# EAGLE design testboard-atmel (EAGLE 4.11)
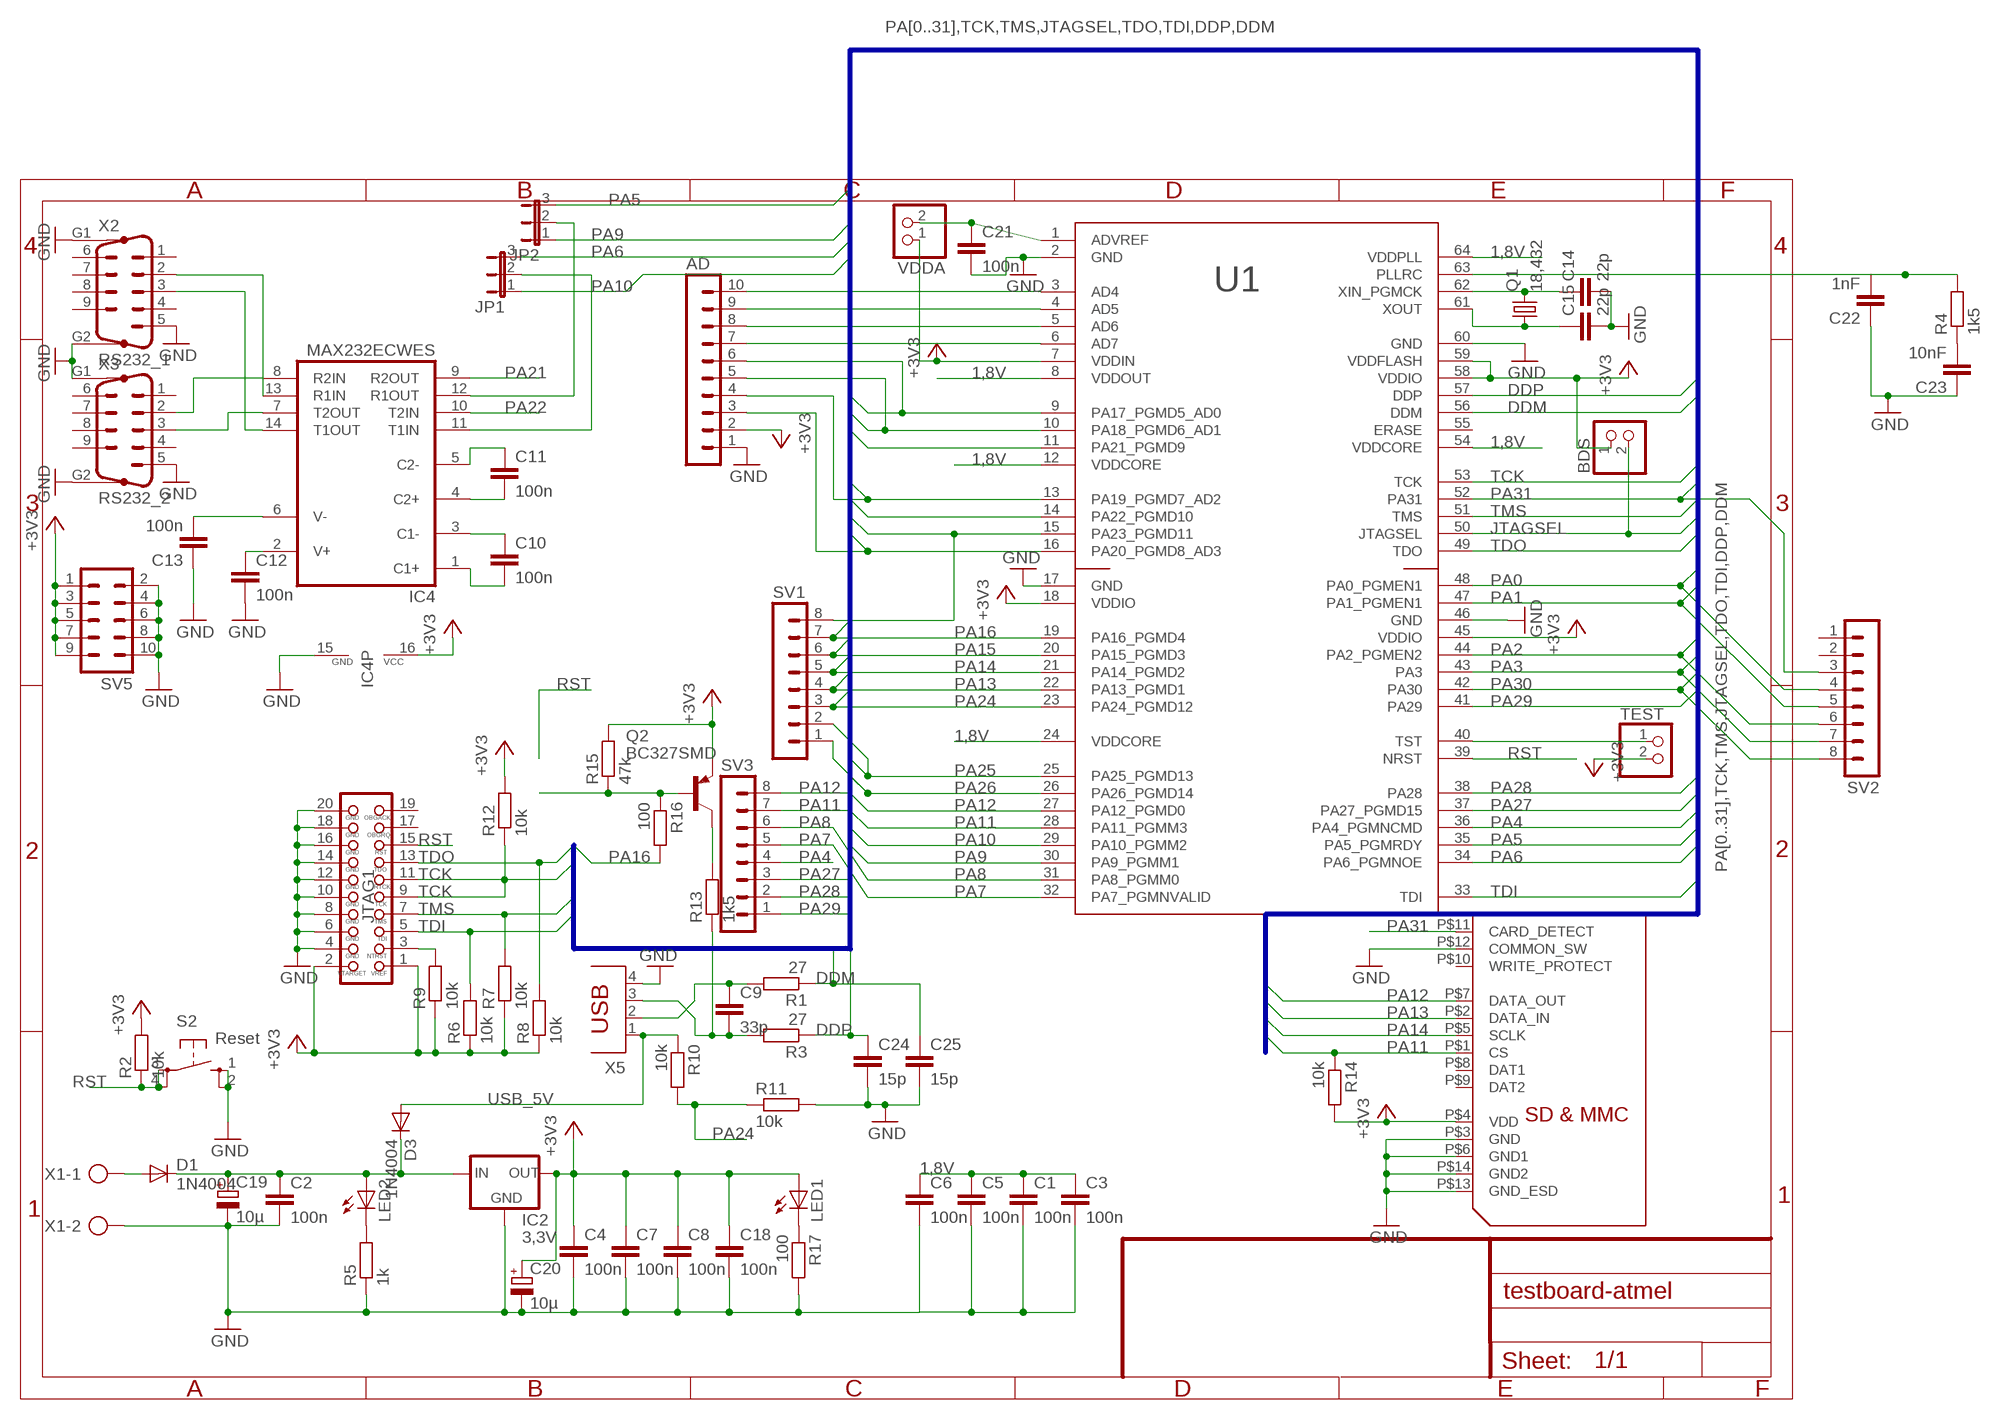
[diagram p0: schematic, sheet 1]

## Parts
AD  MA10-1  [MA10-1]
BDS  PINHD-1X2  [1X02]
C1  100n  C-EUC0805K  [C0805K]
C2  100n  C-EUC0805K  [C0805K]
C3  100n  C-EUC0805K  [C0805K]
C4  100n  C-EUC0805K  [C0805K]
C5  100n  C-EUC0805K  [C0805K]
C6  100n  C-EUC0805K  [C0805K]
C7  100n  C-EUC0805K  [C0805K]
C8  100n  C-EUC0805K  [C0805K]
C9  33p  C-EUC0805K  [C0805K]
C10  100n  C-EUC0805K  [C0805K]
C11  100n  C-EUC0805K  [C0805K]
C12  100n  C-EUC0805K  [C0805K]
C13  100n  C-EUC0805K  [C0805K]
C14  22p  C-EUC0805K  [C0805K]
C15  22p  C-EUC0805K  [C0805K]
C18  100n  C-EUC0805K  [C0805K]
C19  10µ  CPOL-EUE/7260-38W  [E/7260-38W]
C20  10µ  CPOL-EUE/7260-38W  [E/7260-38W]
C21  100n  C-EUC0805K  [C0805K]
C22  1nF  C-EUC0805K  [C0805K]
C23  10nF  C-EUC0805K  [C0805K]
C24  15p  C-EUC0805K  [C0805K]
C25  15p  C-EUC0805K  [C0805K]
D1  1N4004  [DO41-10]
D3  1N4004  [DO41-10]
IC2  3,3V  78XXS  [78XXS]
IC4  MAX232ECWES  [SO16]
JP1  JP2E  [JP2]
JP2  JP2E  [JP2]
JTAG1  JTAG-ARM  [JTAG-ARM]
LED1  LED3MM  [LED3MM]
LED2  LED3MM  [LED3MM]
Q1  18,432  CRYTALHC49U-V  [HC49U-V]
Q2  BC327SMD  [SOT23-BEC]
R1  27  R-EU_M0805  [M0805]
R2  10k  R-EU_M0805  [M0805]
R3  27  R-EU_M0805  [M0805]
R4  1k5  R-EU_M0805  [M0805]
R5  1k  R-EU_M0805  [M0805]
R6  10k  R-EU_M0805  [M0805]
R7  10k  R-EU_M0805  [M0805]
R8  10k  R-EU_M0805  [M0805]
R9  10k  R-EU_M0805  [M0805]
R10  10k  R-EU_M0805  [M0805]
R11  10k  R-EU_M0805  [M0805]
R12  10k  R-EU_M0805  [M0805]
R13  1k5  R-EU_M0805  [M0805]
R14  10k  R-EU_M0805  [M0805]
R15  47k  R-EU_M0805  [M0805]
R16  100  R-EU_M0805  [M0805]
R17  100  R-EU_M0805  [M0805]
S2  Reset  10XX  [B3F-10XX]
SD1  FPS009-2405-0  [FPS009-2405]
SV1  MA08-1  [MA08-1]
SV2  MA08-1  [MA08-1]
SV3  MA08-1  [MA08-1]
SV5  MA05-2  [MA05-2]
TEST  PINHD-1X2  [1X02]
U1  AT91SAM7S64_LQFP64  [LQFP64]
VDDA  PINHD-1X2  [1X02]
X1  AK500/2  [AK500/2]
X2  RS232_1  M09HP  [M09HP]
X3  RS232_2  M09HP  [M09HP]
X5  PN61729  [PN61729]

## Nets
1,8V: C1.1 C3.1 C5.1 C6.1 U1.8(VDDOUT) U1.12(VDDCORE) U1.24(VDDCORE) U1.54(VDDCORE) U1.64(VDDPLL)
+3V3: AD.2 BDS.1 C4.1 C7.1 C8.1 C18.1 C20.+ IC2.OUT IC4.16(VCC) JTAG1.1 JTAG1.2 LED1.A Q2.E R2.2 R6.1 R7.1 R8.1 R9.1 R12.2 R14.2 R15.2 SD1.P$4(VDD) SV5.1 SV5.3 SV5.5 SV5.7 SV5.9 TEST.2 U1.7(VDDIN) U1.18(VDDIO) U1.45(VDDIO) U1.58(VDDIO) U1.59(VDDFLASH) VDDA.1
AD4: AD.10 U1.3(AD4)
AD5: AD.9 U1.4(AD5)
AD6: AD.8 U1.5(AD6)
AD7: AD.7 U1.6(AD7)
DDM: C25.1 R1.1 U1.56(DDM)
DDP: C24.1 R3.1 U1.57(DDP)
JTAGSEL: BDS.2 U1.50(JTAGSEL)
N$1: D1.A X1.1
N$2: C2.1 C19.+ D1.C D3.C IC2.IN LED2.A
N$3: C11.1 IC4.5(C2-)
N$4: C9.2 R3.2 R13.1 X5.3
N$5: TEST.1 U1.40(TST)
N$6: C11.2 IC4.4(C2+)
N$7: C10.1 IC4.3(C1-)
N$8: C10.2 IC4.1(C1+)
N$9: C12.1 IC4.2(V+)
N$10: C13.2 IC4.6(V-)
N$11: C15.1 Q1.1 U1.61(XOUT)
N$12: C14.1 Q1.2 U1.62(XIN_PGMCK)
N$13: LED2.K(C) R5.2
N$14: LED1.K(C) R17.1
N$15: AD.1 C1.2 C2.2 C3.2 C4.2 C5.2 C6.2 C7.2 C8.2 C12.2 C13.1 C14.2 C15.2 C18.2 C19.- C20.- C21.2 C22.1 C23.1 C24.2 C25.2 IC2.GND IC4.15(GND) JTAG1.4 JTAG1.6 JTAG1.8 JTAG1.10 JTAG1.12 JTAG1.14 JTAG1.16 JTAG1.18 JTAG1.20 R5.1 R11.2 R17.2 S2.1 S2.2 SD1.P$3(GND) SD1.P$6(GND1) SD1.P$12(COMMON_SW) SD1.P$13(GND_ESD) SD1.P$14(GND2) SV5.2 SV5.4 SV5.6 SV5.8 SV5.10 U1.2(GND) U1.17(GND) U1.46(GND) U1.60(GND) X1.2 X2.5 X2.G1 X2.G2 X3.5 X3.G1 X3.G2 X5.4 ; supply symbol labelled GND
N$16: IC4.13(R1IN) X2.2
N$17: JTAG1.3 R9.2
N$18: C21.1 U1.1(ADVREF) VDDA.2
N$20: Q2.C R13.2
N$23: Q2.B R15.1 R16.1
N$24: C9.1 R1.2 X5.2
N$26: IC4.14(T1OUT) X2.3
N$27: IC4.8(R2IN) X3.2
N$28: IC4.7(T2OUT) X3.3
N$33: C23.2 R4.1
N$35: C22.2 R4.2 U1.63(PLLRC)
PA0: SV2.4 U1.48(PA0_PGMEN1)
PA1: SV2.5 U1.47(PA1_PGMEN1)
PA2: SV2.6 U1.44(PA2_PGMEN2)
PA3: SV2.7 U1.43(PA3)
PA4: SV3.4 U1.36(PA4_PGMNCMD)
PA5: JP2.3 U1.35(PA5_PGMRDY)
PA6: JP1.3 U1.34(PA6_PGMNOE)
PA7: SV3.5 U1.32(PA7_PGMNVALID)
PA8: SV3.6 U1.31(PA8_PGMM0)
PA9: JP2.1 U1.30(PA9_PGMM1)
PA10: JP1.1 U1.29(PA10_PGMM2)
PA11: R14.1 SD1.P$1(CS) SV3.7 U1.28(PA11_PGMM3)
PA12: SD1.P$7(DATA_OUT) SV3.8 U1.27(PA12_PGMD0)
PA13: SD1.P$2(DATA_IN) SV1.4 U1.22(PA13_PGMD1)
PA14: SD1.P$5(SCLK) SV1.5 U1.21(PA14_PGMD2)
PA15: SV1.6 U1.20(PA15_PGMD3)
PA16: R16.2 SV1.7 U1.19(PA16_PGMD4)
PA17: AD.6 U1.9(PA17_PGMD5_AD0)
PA18: AD.5 U1.10(PA18_PGMD6_AD1)
PA19: AD.4 U1.13(PA19_PGMD7_AD2)
PA20: AD.3 U1.16(PA20_PGMD8_AD3)
PA21: IC4.9(R2OUT) U1.11(PA21_PGMD9)
PA22: IC4.10(T2IN) U1.14(PA22_PGMD10)
PA23: SV1.8 U1.15(PA23_PGMD11)
PA24: R10.2 R11.1 SV1.3 U1.23(PA24_PGMD12)
PA25: SV1.2 U1.25(PA25_PGMD13)
PA26: SV1.1 U1.26(PA26_PGMD14)
PA27: SV3.3 U1.37(PA27_PGMD15)
PA28: SV3.2 U1.38(PA28)
PA29: SV3.1 U1.41(PA29)
PA30: SV2.8 U1.42(PA30)
PA31: SD1.P$11(CARD_DETECT) SV2.3 U1.52(PA31)
R1OUT: IC4.12(R1OUT) JP2.2
RST: JTAG1.15 R2.1 S2.3 S2.4 U1.39(NRST)
T1IN: IC4.11(T1IN) JP1.2
TCK: JTAG1.9 JTAG1.11 R12.1 U1.53(TCK)
TDI: JTAG1.5 R6.2 U1.33(TDI)
TDO: JTAG1.13 R8.2 U1.49(TDO)
TMS: JTAG1.7 R7.2 U1.51(TMS)
USB_5V: D3.A R10.1 X5.1
Unconnected: JTAG1.17 JTAG1.19 SD1.P$8(DAT1) SD1.P$9(DAT2) SD1.P$10(WRITE_PROTECT) SV2.1 SV2.2 U1.55(ERASE) X2.1 X2.4 X2.6 X2.7 X2.8 X2.9 X3.1 X3.4 X3.6 X3.7 X3.8 X3.9

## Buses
PA[0..31],TCK,TMS,JTAGSEL,TDO,TDI,DDP,DDM

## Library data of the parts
AD = con-lstb:MA10-1: PIN HEADER
BDS TEST VDDA = pinhead:PINHD-1X2: PIN HEADER
C1-C15 C18 C21-C25 = rcl:C-EU: CAPACITOR, European symbol
C19 C20 = rcl:CPOL-EU: POLARIZED CAPACITOR, European symbol
D1 D3 = diode:1N4004: DIODE
IC2 = v-reg:78XXS: VOLTAGE REGULATOR
IC4 = maxim-6b:MAX232ECWE: RS232 TRANSEIVER
JP1 JP2 = jumper:JP2E: JUMPER
JTAG1 = philips-6:JTAG-ARM
LED1 LED2 = led:LED: LED
Q1 = crystal:CRYTAL: CRYSTAL
Q2 = transistor-pnp:BC327*: PNP Transistror
R1-R17 = rcl:R-EU_: RESISTOR, European symbol
S2 = KEY_B:10XX
SD1 = con-yamaichi:FPS009-2405-0
SV1-SV3 = con-lstb:MA08-1: PIN HEADER
SV5 = con-lstb:MA05-2: PIN HEADER
U1 = atmel_prototype_header:AT91SAM7S64: Atmel AT91 ARM Thumb-based Microcontroller. LQFP64 package.
X1 = con-ptr500:AK500/2: CONNECTOR
X2 X3 = con-subd:M09HP: SUB-D
X5 = con-berg:PN61729: BERG

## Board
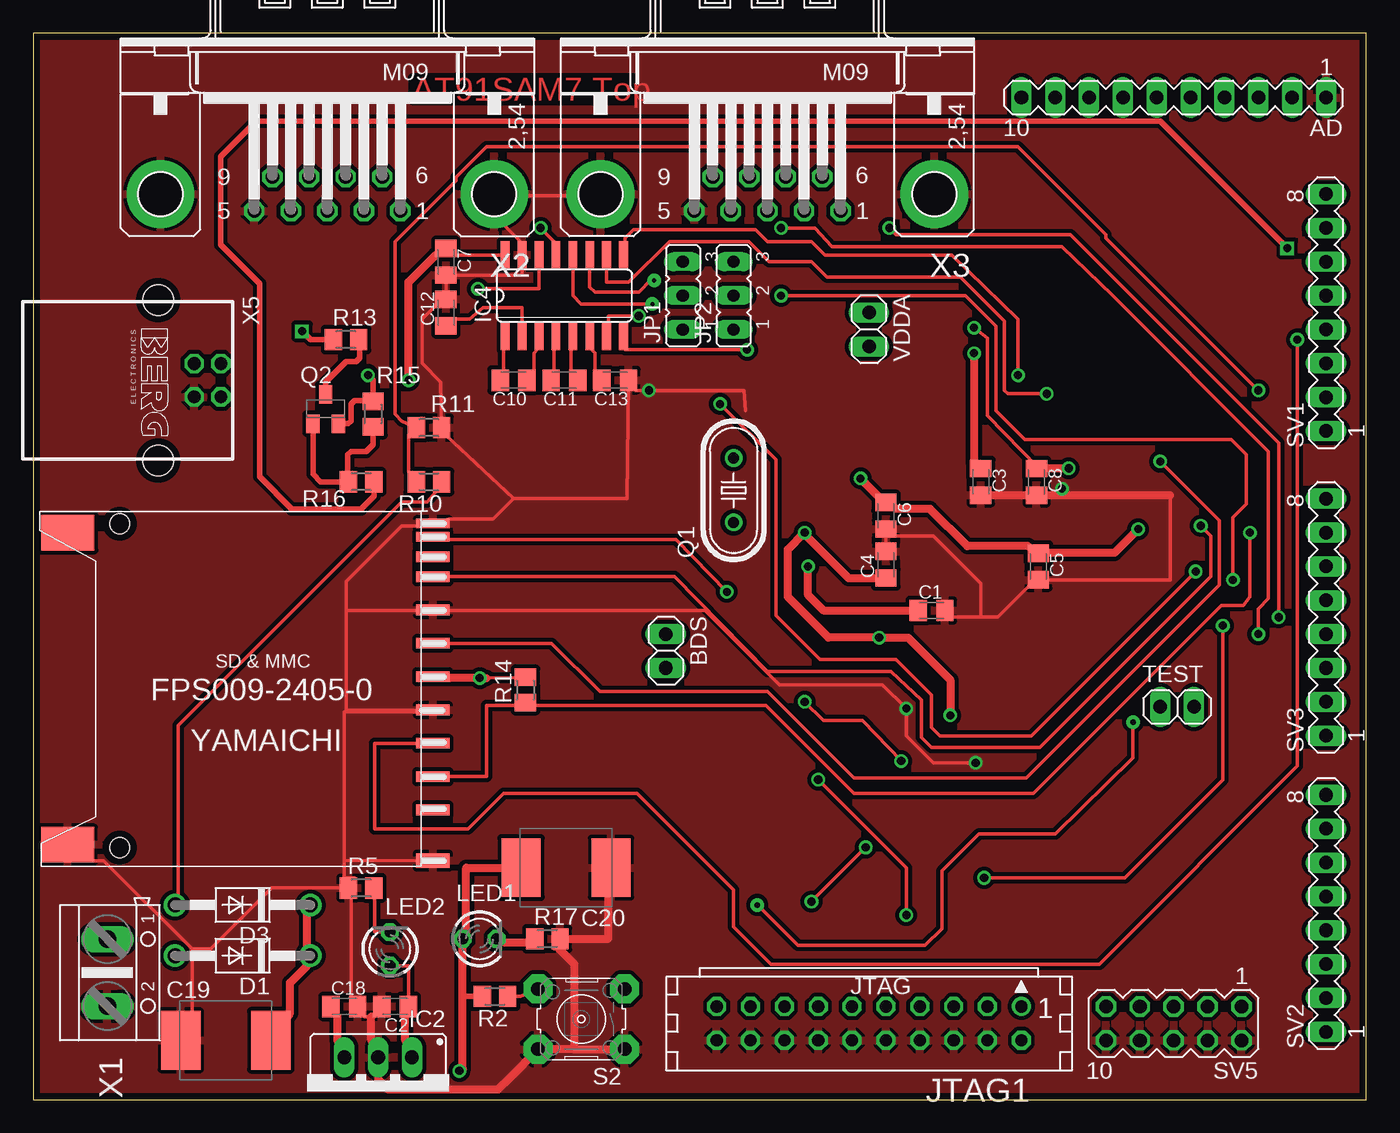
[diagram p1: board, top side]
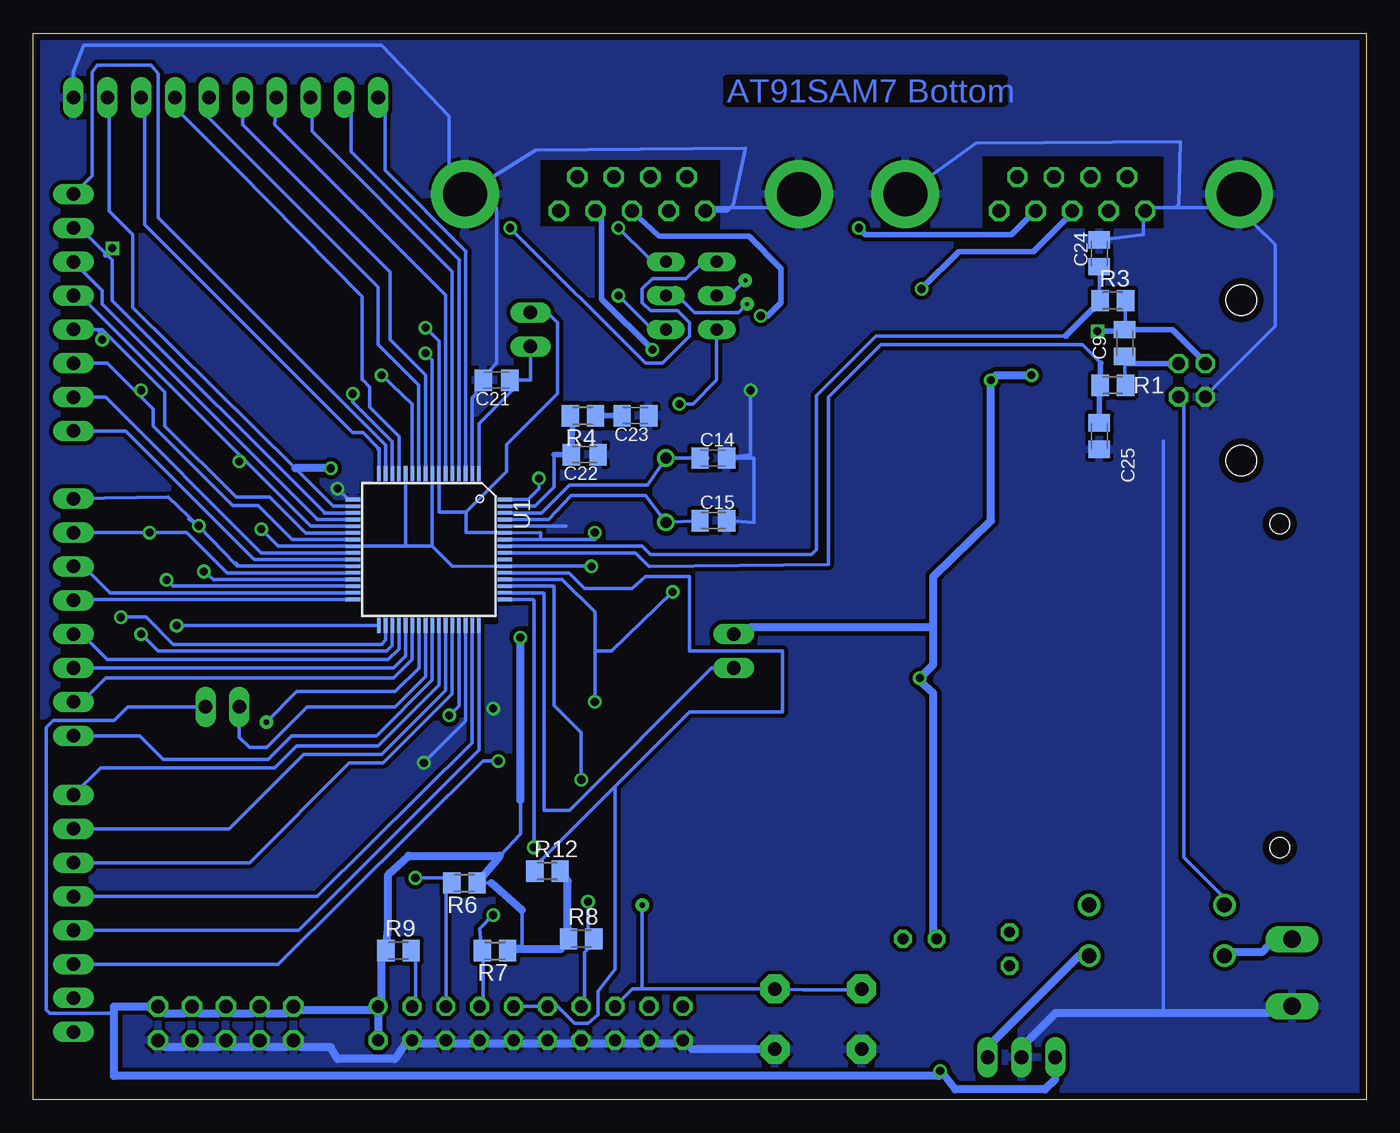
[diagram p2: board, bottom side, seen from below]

Size 100 x 80 mm. Coordinates in mm from the lower left corner, seen from the top.
Outline: 0,0 100,0 100,80 0,80 0,0
Copper layers (1*16): Top 0.035mm / dielectric 1.5mm / Bottom 0.035mm
Design rules "default": minimum track width 8mil, minimum drill 24mil, track to track 12mil, track to pad 12mil, pad to pad 8mil, via to via 12mil, smd to smd 8mil, copper to edge 20mil, drill to drill 8mil, minimum pad ring 10mil, minimum via ring 8mil, stop-mask expansion 4mil, vias tented up to drill 0mil, thermal gap 10mil
bRestrict: area 65.1,36.1 to 75.5,46.4; area 15.2,65.4 to 28.8,70.7; area 48.5,65.5 to 61.9,70.5; area 65.1,35.7 to 75.5,46
vRestrict: area 34.8,57.8 to 44.9,62.9; area 13.2,1.9 to 15.7,7; area 37.3,15.9 to 39.8,20.9

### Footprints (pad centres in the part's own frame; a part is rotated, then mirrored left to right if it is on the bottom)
MA10-1 = drill 1.016 long: 1 -11.43,0; 2 -8.89,0; 3 -6.35,0; 4 -3.81,0; 5 -1.27,0; 6 1.27,0; 7 3.81,0; 8 6.35,0; 9 8.89,0; 10 11.43,0
1X02 = drill 1.016 long: 1 -1.27,0; 2 1.27,0
C0805K = smd 1.3 x 1.6: 1 -1,0; 2 1,0
E/7260-38W = smd 2.95 x 4.4: + 3.375,0; - -3.375,0
DO41-10 = drill 1.118 round: A 5.08,0; C -5.08,0
78XXS = drill 1.016 long: GND 0,-2.54; IN -2.54,-2.54; OUT 2.54,-2.54
SO16 = smd 0.66 x 2.032: 1 -4.445,-3.073; 2 -3.175,-3.073; 3 -1.905,-3.073; 4 -0.635,-3.073; 5 0.635,-3.073; 6 1.905,-3.073; 7 3.175,-3.073; 8 4.445,-3.073; 9 4.445,3.073; 10 3.175,3.073; 11 1.905,3.073; 12 0.635,3.073; 13 -0.635,3.073; 14 -1.905,3.073; 15 -3.175,3.073; 16 -4.445,3.073
JP2 = drill 0.914 long: 1 -2.54,0; 2 0,0; 3 2.54,0
JTAG-ARM = drill 0.914 round: 1 -11.43,-1.27 | drill 0.914 octagon: 2 -11.43,1.27; 3 -8.89,-1.27; 4 -8.89,1.27; 5 -6.35,-1.27; 6 -6.35,1.27; 7 -3.81,-1.27; 8 -3.81,1.27; 9 -1.27,-1.27; 10 -1.27,1.27; 11 1.27,-1.27; 12 1.27,1.27; 13 3.81,-1.27; 14 3.81,1.27; 15 6.35,-1.27; 16 6.35,1.27; 17 8.89,-1.27; 18 8.89,1.27; 19 11.43,-1.27; 20 11.43,1.27
LED3MM = drill 0.813 octagon: A -1.27,0; K 1.27,0
HC49U-V = drill 0.813 round: 1 -2.413,0; 2 2.413,0
SOT23-BEC = smd 1 x 1.4: B -0.95,-1.1; C 0,1.1; E 0.95,-1.1
M0805 = smd 1.3 x 1.6: 1 -0.95,0; 2 0.95,0
B3F-10XX = drill 1.016 pad 2.159 octagon: 1 -3.379,2.312; 2 3.123,2.312; 3 -3.379,-2.209; 4 3.123,-2.209
FPS009-2405 = smd 2.5 x 0.8: P$1 -13,6.88; P$2 -13,4.38; P$3 -13,1.88; P$4 -13,-0.62; P$5 -13,-3.12; P$6 -13,-5.62; P$7 -13,-8.12; P$8 -13,-9.62; P$9 -13,9.38 | smd 4 x 2.65: P$10 14.4,-11.42; P$14 14.4,11.98 | smd 2.5 x 0.7: P$11 -13,-11.12; P$12 -13,-12.12 | smd 2.5 x 1.1: P$13 -13,13.18 | hole 1.5: 10.5,12.2; 10.5,-12.1
MA08-1 = drill 1.016 long: 1 -8.89,0; 2 -6.35,0; 3 -3.81,0; 4 -1.27,0; 5 1.27,0; 6 3.81,0; 7 6.35,0; 8 8.89,0
MA05-2 = drill 1.016 octagon: 1 -5.08,-1.27; 2 -5.08,1.27; 3 -2.54,-1.27; 4 -2.54,1.27; 5 0,-1.27; 6 0,1.27; 7 2.54,-1.27; 8 2.54,1.27; 9 5.08,-1.27; 10 5.08,1.27
LQFP64 = smd 1.1 x 0.285: 1 -5.7,3.75; 2 -5.7,3.25; 3 -5.7,2.75; 4 -5.7,2.25; 5 -5.7,1.75; 6 -5.7,1.25; 7 -5.7,0.75; 8 -5.7,0.25; 9 -5.7,-0.25; 10 -5.7,-0.75; 11 -5.7,-1.25; 12 -5.7,-1.75; 13 -5.7,-2.25; 14 -5.7,-2.75; 15 -5.7,-3.25; 16 -5.7,-3.75; 33 5.7,-3.75; 34 5.7,-3.25; 35 5.7,-2.75; 36 5.7,-2.25; 37 5.7,-1.75; 38 5.7,-1.25; 39 5.7,-0.75; 40 5.7,-0.25; 41 5.7,0.25; 42 5.7,0.75; 43 5.7,1.25; 44 5.7,1.75; 45 5.7,2.25; 46 5.7,2.75; 47 5.7,3.25; 48 5.7,3.75 | smd 0.285 x 1.1: 17 -3.75,-5.7; 18 -3.25,-5.7; 19 -2.75,-5.7; 20 -2.25,-5.7; 21 -1.75,-5.7; 22 -1.25,-5.7; 23 -0.75,-5.7; 24 -0.25,-5.7; 25 0.25,-5.7; 26 0.75,-5.7; 27 1.25,-5.7; 28 1.75,-5.7; 29 2.25,-5.7; 30 2.75,-5.7; 31 3.25,-5.7; 32 3.75,-5.7; 49 3.75,5.7; 50 3.25,5.7; 51 2.75,5.7; 52 2.25,5.7; 53 1.75,5.7; 54 1.25,5.7; 55 0.75,5.7; 56 0.25,5.7; 57 -0.25,5.7; 58 -0.75,5.7; 59 -1.25,5.7; 60 -1.75,5.7; 61 -2.25,5.7; 62 -2.75,5.7; 63 -3.25,5.7; 64 -3.75,5.7
AK500/2 = drill 1.321 long: 1 -2.515,0; 2 2.515,0
M09HP = drill 1.016 octagon: 1 -5.486,1.27; 2 -2.743,1.27; 3 0,1.27; 4 2.743,1.27; 5 5.486,1.27; 6 -4.115,-1.27; 7 -1.372,-1.27; 8 1.372,-1.27; 9 4.115,-1.27 | drill 3.302 pad 5.08 round: G1 -12.522,0; G2 12.522,0
PN61729 = drill 0.95 octagon: 1 1.25,4.71; 2 -1.25,4.71; 3 -1.25,2.71; 4 1.25,2.71 | hole 2.3: -6.02,0; 6.02,0

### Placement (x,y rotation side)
AD  85.56,75.18 180 top
BDS  47.46,33.65 270 top
C1  67.4,36.7 0 top
C2  27.14,6.98 180 top
C3  71.08,46.35 270 top
C4  63.97,40.13 90 top
C5  75.4,40 270 top
C6  63.97,43.81 270 top
C7  30.95,62.86 270 top
C8  75.27,46.35 270 top
C9  18.12,56.76 90 bottom
C10  36.03,53.97 180 top
C11  39.84,53.97 180 top
C12  30.95,59.05 90 top
C13  43.65,53.97 180 top
C14  48.98,48.13 0 bottom
C15  48.98,43.43 0 bottom
C18  23.33,6.98 0 top
C19  14.44,4.44 0 top
C20  39.97,17.39 180 top
C21  65.24,53.97 180 bottom
C22  58.64,48.38 180 bottom
C23  54.83,51.3 180 bottom
C24  20.03,63.5 90 bottom
C25  20.03,49.78 270 bottom
D1  15.71,10.79 180 top
D3  15.71,14.6 180 top
IC2  25.87,0.63 180 top
IC4  39.84,60.32 0 top
JP1  48.73,60.32 90 top
JP2  52.54,60.32 90 top
JTAG1  62.7,5.71 180 top
LED1  33.49,12.06 0 top
LED2  26.76,11.3 90 top
Q1  52.54,45.72 90 top
Q2  21.93,51.81 0 top
R1  19.01,53.59 0 bottom
R2  34.63,7.74 180 top
R3  19.01,59.94 0 bottom
R4  58.76,51.3 180 bottom
R5  24.6,15.87 0 top
R6  67.65,16.25 180 bottom
R7  65.37,11.17 180 bottom
R8  58.89,12.06 0 bottom
R9  72.61,11.17 0 bottom
R10  29.68,46.35 180 top
R11  29.68,50.41 0 top
R12  61.43,17.14 0 bottom
R13  23.46,57.02 0 top
R14  36.92,30.73 90 top
R15  25.49,51.43 90 top
R16  24.6,46.35 0 top
R17  38.57,12.06 0 top
S2  40.98,6.09 180 top
SD1  16.98,31.11 180 top
SV1  96.99,59.05 90 top
SV2  96.99,13.97 90 top
SV3  96.99,36.19 90 top
SV5  85.56,5.71 180 top
TEST  85.81,29.46 0 top
U1  70.32,41.27 270 bottom
VDDA  62.7,57.78 270 top
X1  5.55,9.52 270 top
X2  22.06,67.94 180 top
X3  55.08,67.94 180 top
X5  9.36,53.97 270 top

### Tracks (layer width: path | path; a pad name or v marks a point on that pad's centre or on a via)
1,8V  (via drill 0.61)
  Top 0.254: 74.64,41.52 C5.1 75.4,41.02 | 64.73,44.32 C6.1 63.86,44.81 | C3.1 71.08,47.37 70.57,47.75
  Top 0.61: 74.64,41.52 70.07,41.52 67.27,44.32 64.73,44.32 | 63.86,44.81 v62.06,46.6 | v70.57,56 70.57,47.75 | v58.13,40 58.13,37.84 59.27,36.7 C1.1 | v82.89,42.79 81.11,41.02 75.4,41.02
  Bottom 0.254: 70.07,41.52 68.54,40 U1.54 57.89,40.02 v58.13,40 | 70.07,41.52 70.07,46.6 U1.8 70.07,47.37 70.07,55.49 v70.57,56 | 70.07,41.52 72.1,41.52 | 72.1,41.52 75.65,41.52 U1.24 76.03,41.52 81.62,41.52 v82.89,42.79 | U1.12 72.07,41.55 72.1,41.52 | U1.64 62.89,45.02 62.06,45.84 v62.06,46.6
+3V3  (via drill 0.61)
  Top 0.254: 22.82,6.22 C18.1 | LED1.A 32.47,12.57 | 34,31.62 R14.2 | 31.2,31.62 SD1.P$4 | IC4.16 35.27,63.37 31.71,63.37 C7.1 30.19,63.37 | C8.1 75.27,47.37 75.4,47.37 71.59,51.3 71.59,57.15 v70.57,57.91 | v57.87,42.54 57.87,42.41
  Top 0.406: Q2.E 23.63,50.71 23.84,50.92 23.84,52.19 24.09,52.45 25.36,52.45 25.43,52.38 R15.2 25.49,53.97 v25.11,54.35 | v31.97,2.15 32.22,2.41 32.22,2.28 | 32.22,7.74 R2.2
  Top 0.61: 22.82,6.22 22.82,4.44 IC2.OUT | 32.22,2.28 32.22,7.74 LED1.A | 32.47,12.57 32.47,17.39 C20.+ | 31.2,31.62 v33.49,31.62 34,31.62 | 30.19,63.37 28.16,61.34 v28.16,53.97 | 75.4,47.37 v77.69,47.37 | C4.1 61.16,39.13 57.87,42.41 | v68.8,28.82 68.8,31.49 65.62,34.67 v63.46,34.67 59.65,34.67 56.6,37.71 56.6,41.27 v57.87,42.54
  Bottom 0.254: 23.33,1.52 IC2.OUT | 46.19,35.43 BDS.1 | VDDA.1 61.43,59.05 60.67,58.29 60.67,52.95 64.48,49.14 64.48,47.11 67.53,44.06 | AD.2 94.32,75.31 94.32,66.67 92.55,64.89 92.55,59.43 80.35,47.37 77.51,44.52 U1.18 | 73.88,11.3 R9.1 | 73.88,7.49 JTAG1.1 74.64,6.73 | 80.99,6.47 SV5.9 79.97,6.73 | SV5.7 82.51,6.47 | 87.59,6.47 SV5.3 88.61,6.47 | 86.07,6.47 SV5.5 | 90.13,6.47 SV5.1 90.64,7.11 90.77,7.11 90.77,6.98 | 60.41,11.3 R8.1 59.91,12.82 | 63.72,11.3 R7.1 | 61.94,42.03 61.94,42.54 U1.59 64.99,42.54 67.53,42.54 67.53,44.06 | v57.87,42.54 57.87,42.03 61.94,42.03 | 61.94,42.03 U1.58 | 63.34,14.22 63.34,11.3 | R6.1 65.62,16.25 | 32.22,2.41 v31.97,2.15 31.84,2.03 32.09,1.77 | U1.45 68.07,29.55 v68.8,28.82 | 67.53,44.06 69.56,44.06 69.56,46.6 U1.7 69.57,56.9 v70.57,57.91 | v28.16,53.97 27.77,54.35 | 63.46,22.47 63.46,19.93 64.99,18.28 | TEST.2 92.93,29.46 93.94,28.44 98.51,28.44 99.02,27.93 99.02,6.73 98.77,6.47 93.94,6.47
  Bottom 0.61: 23.33,1.52 24.09,0.76 30.82,0.76 31.84,2.03 | 32.47,35.43 46.19,35.43 | v28.16,53.97 28.16,43.43 32.47,39.24 32.47,35.43 | 32.47,35.43 32.47,32.63 v33.49,31.62 33.49,31.36 32.47,30.47 32.47,12.57 LED1.A | 73.88,7.49 73.88,11.3 | 82.51,6.47 80.99,6.47 | SV5.5 85.05,6.47 83.53,6.47 SV5.7 | 87.59,6.47 86.07,6.47 | 90.13,6.47 88.61,6.47 | 79.97,6.73 74.64,6.73 | 63.34,11.3 63.72,11.3 | 63.34,11.3 60.41,11.3 | 59.91,12.82 59.91,16.38 R12.2 | 63.46,22.47 v63.46,34.67 | R6.1 64.99,18.28 71.84,18.28 73.37,16.89 73.37,12.82 R9.1 | 65.62,16.25 63.34,14.22 | 63.34,11.3 R7.1 | v77.69,47.37 80.35,47.37 | 27.77,54.35 v25.11,54.35 | JTAG1.1 JTAG1.2 | 32.09,1.77 93.94,1.77 93.94,6.47 93.94,6.98 90.77,6.98
AD4
  Bottom 0.254: AD.10 73.62,75.56 73.62,69.72 67.53,63.62 67.57,63.58 U1.3
AD5
  Bottom 0.254: 68.07,63.02 68.03,62.99 | AD.9 76.16,75.56 76.16,71.11 68.16,63.11 68.07,63.02 | U1.4 68.07,63.02
AD6
  Bottom 0.254: AD.8 79.08,75.31 79.08,72.64 68.57,62.13 U1.5
AD7
  Bottom 0.254: 81.62,75.43 AD.7 81.88,73.15 69.07,60.34 U1.6
DDM
  Bottom 0.254: U1.56 64.22,41.02 54.83,41.02 53.81,40 40.35,40.13 40.35,52.7 36.41,56.64 21.3,56.64 19.9,55.24
  Bottom 0.406: C25.1 20.03,53.59 R1.1 19.96,55.18 19.9,55.24
DDP
  Bottom 0.254: 22.5,57.27 36.79,57.27 41.24,52.83 41.24,41.27 41.62,40.89 53.68,40.89 54.32,41.52 64.22,41.52 U1.57 | C24.1 20.03,59.81 R3.1 | 19.9,59.81 19.77,59.81
  Bottom 0.406: R3.1 19.9,59.81 20.41,59.3 20.54,59.3 22.57,57.27 22.5,57.27
JTAGSEL
  Bottom 0.254: BDS.2 49.11,32.38 59.78,21.71 61.68,21.71 61.68,37.97 61.74,38.02 U1.50
N$1
  Bottom 0.61: D1.A 9.87,11.04 7.84,11.04 7.33,11.55 X1.1
N$2
  Top 0.254: 27.9,6.22 C2.1 28.16,7.74 28.16,10.03 LED2.A | IC2.IN 27.9,4.44
  Top 0.61: 27.9,4.44 27.9,6.22 | D3.C 20.54,13.84 20.54,11.55 D1.C 20.54,10.03 19.27,8.76 19.27,6.47 C19.+
  Bottom 0.254: D1.C 21.55,10.79
  Bottom 0.61: 21.55,10.79 27.9,4.44 IC2.IN
N$3
  Top 0.254: C11.1 40.35,54.73 40.35,56.26 IC4.5
N$4  (via drill 0.61)
  Top 0.406: R13.1 20.79,57.02 v20.15,57.65
  Bottom 0.254: C9.2 18.12,57.65 18.12,57.4 18.06,57.4 R3.2
  Bottom 0.406: X5.3 12.05,55.22 12.03,55.24 14.55,57.76 C9.2 | 18.12,57.65 v20.15,57.65
N$5
  Bottom 0.254: U1.40 70.57,35.17 70.57,31.74 72.86,29.46 79.46,29.46 82.51,26.41 83.78,26.41 84.54,27.17 TEST.1
N$6
  Top 0.254: C11.2 39.08,54.73 39.08,56.26 IC4.4
N$7
  Top 0.254: C10.1 37.55,54.73 37.55,56 37.81,56.26 IC4.3
N$8
  Top 0.254: C10.2 35.27,54.73 35.27,56.26 IC4.1
N$9
  Top 0.254: C12.1 31.71,58.54 32.73,58.54 33.74,59.43 36.66,59.43 IC4.2
N$10
  Top 0.254: C13.2 42.13,54.73 42.13,56 41.87,56.26 IC4.6
N$11
  Bottom 0.254: C15.1 Q1.1 54.06,45.33 59.65,45.33 61.34,43.52 U1.61
N$12
  Bottom 0.254: 49.37,48.13 C14.1 Q1.2 53.94,46.1 59.78,46.1 61.85,44.02 U1.62
N$13
  Top 0.254: R5.2 25.62,15.11 25.62,12.57 LED2.K
N$14
  Top 0.254: 37.05,11.81 R17.1
  Top 0.61: 37.05,11.81 35.27,11.81 LED1.K
N$15  (via drill 0.61, 0.61 pad 1.02)
  Top 0.254: X3.G2 40.22,67.81 37.17,67.81 X2.G1 35.27,65.65 36.54,64.38 IC4.15 36.66,61.84 31.71,61.84 C7.2 C12.2 30.19,59.56 29.17,58.54 29.17,55.24 30.57,53.84 R11.2 30.31,50.41 36.03,45.08 | 43.14,15.11 42.76,16.76 C20.- | R17.2 39.08,11.3 39.46,11.3 | 11.9,11.3 5.3,17.9 4.53,17.9 SD1.P$14 | 11.9,11.3 11.9,6.47 C19.- | C2.2 25.62,6.22 25.36,6.22 24.85,6.22 C18.2 23.84,7.74 23.84,15.11 R5.1 | 23.33,17.9 23.33,16.63 24.09,16.63 R5.1 | 23.33,17.9 SD1.P$13 | 25.36,4.44 IC2.GND 25.87,1.52 | 11.9,11.3 13.3,11.3 17.87,15.87 R5.1 | 71.08,36.19 72.35,36.19 74.64,38.48 C5.2 75.4,38.98 85.31,38.98 85.31,45.33 | 71.08,36.19 69.05,36.19 68.54,36.7 C1.2 | 53.43,51.68 53.3,53.21 v46.19,53.21 45.17,53.21 C13.1 44.54,45.08 36.03,45.08 | 71.08,36.19 71.08,38.73 67.53,42.29 64.73,42.29 C6.2 | 23.46,36.7 50.38,36.7 55.97,31.11 63.72,31.11 v65.49,29.33 65.49,27.3 67.53,25.27 v70.7,25.27 | 23.46,36.7 28.92,36.7 SD1.P$6 | 23.46,36.7 23.46,29.2 28.92,29.2 28.92,29.59 SD1.P$3 28.92,29.08 23.33,29.08 23.33,17.9 | 23.46,36.7 23.46,38.86 27.65,43.05 28.92,43.05 SD1.P$12 31.2,43.56 34.51,43.56 36.03,45.08 | C3.2 71.1,45.33 75.27,45.33 C8.2 76.69,45.35 v77.18,45.84 | C6.2 63.97,43.05 | 37.81,3.8 37.83,3.78 S2.2 | 40.6,3.8 40.48,3.8 40.5,3.78 | C6.2 C4.2
  Top 0.61: 43.14,15.11 43.14,12.06 R17.2 | 25.36,4.44 25.36,6.22 | 25.87,1.52 26.63,0.76 34.89,0.76 35.78,1.65 S2.2 | 85.31,45.33 71.1,45.33 | 39.46,11.3 40.6,10.16 40.6,3.8 | 37.81,3.8 40.48,3.8 | 40.5,3.78 S2.1
  Bottom 0.254: AD.1 96.99,77.08 96.23,79.12 73.88,79.12 68.8,73.78 68.8,70.23 X3.G1 | X3.G1 65.24,66.92 65.24,55.24 65.75,54.73 C21.2 66.76,53.21 66.76,52.95 67.07,52.65 U1.2 | C24.2 16.73,64.89 16.73,66.16 X2.5 | X2.G2 10.63,65.91 | X5.4 11.65,53.21 6.82,58.03 6.82,64.13 8.34,65.65 X2.G2 | X2.5 15.96,66.92 11.9,66.92 X2.G2 | X3.G2 44.92,66.92 48.98,66.92 X3.5 47.97,66.67 47.46,67.18 46.57,71.37 62.32,71.24 X3.G1 | X2.5 17.23,66.92 14.31,66.92 14.06,67.18 13.93,71.88 29.3,71.75 X2.G1 | 80.99,3.93 SV5.10 79.97,3.93 | 85.05,3.93 SV5.6 86.07,3.93 | SV5.8 83.53,3.93 | SV5.4 88.61,3.93 | JTAG1.20 51.78,4.19 | 53.3,4.19 JTAG1.18 | JTAG1.16 56.86,4.19 | 60.92,4.19 JTAG1.12 | JTAG1.14 59.4,4.19 | 66,4.19 JTAG1.8 | JTAG1.10 64.48,4.19 | 71.08,4.19 JTAG1.4 72.1,4.19 | JTAG1.6 69.56,4.19 | JTAG1.20 50.76,4.19 | v77.18,45.84 76.42,45.08 U1.17 | C15.2 45.94,43.3 45.94,48.13 C14.2 46.19,48.38 v46.19,53.21 | C23.1 53.43,51.68 | U1.46 67.57,28.4 v70.7,25.27 | 50.61,3.78 JTAG1.20 | 15.2,6.34 15.2,6.47 15.2,49.4 | U1.60 60.06,43.02 60.03,43.05
  Bottom 0.61: 80.99,3.93 82.51,3.93 SV5.8 | 83.53,3.93 85.05,3.93 | 86.07,3.93 87.59,3.93 SV5.4 | 88.61,3.93 90.13,3.93 SV5.2 | 51.78,4.19 53.3,4.19 | JTAG1.16 55.84,4.19 54.32,4.19 JTAG1.18 | 56.86,4.19 58.38,4.19 JTAG1.14 | 59.4,4.19 60.92,4.19 | JTAG1.10 63.46,4.19 61.94,4.19 JTAG1.12 | 64.48,4.19 66,4.19 | JTAG1.6 68.54,4.19 67.02,4.19 JTAG1.8 | 69.56,4.19 71.08,4.19 | 79.97,3.93 77.69,3.93 77.18,3.04 72.86,3.04 72.1,4.19 | X1.2 7.33,6.47 15.2,6.47 23.33,6.47 25.36,4.44 IC2.GND | S2.1 50.61,3.78
  pour Bottom: -1.56,81.15 -0.8,-0.77 100.93,-0.77 100.93,80.39
  pour Top: -1.44,81.15 -0.67,-0.64 100.93,-0.64 100.93,80.51
N$16  (via drill 0.61)
  Top 0.254: v38.06,65.4 39.08,64.38 IC4.13
  Bottom 0.254: 25.36,66.16 X2.2
  Bottom 0.406: v38.06,65.4 37.55,64.89 26.63,64.89 25.36,66.16
N$17
  Bottom 0.254: R9.2 71.34,11.3 71.34,7.49 JTAG1.3
N$18
  Bottom 0.254: VDDA.2 62.7,53.97 C21.1 64.1,53.21 66.57,50.73 U1.1
N$20
  Top 0.406: Q2.C 21.93,53.84 23.46,55.37 24.22,55.37 24.47,55.62 24.47,57.02 R13.2
N$23
  Top 0.406: Q2.B 20.98,46.92 21.55,46.35 23.58,46.35 | 23.71,46.35 R16.1 23.58,46.35 | R15.1 25.49,49.14 24.98,48.64 23.84,48.64 23.58,48.38 23.58,46.35
N$24
  Bottom 0.254: 18.14,55.51 18.38,56 | 18.14,55.51 C9.1 | R1.2 18.12,55.24 18.12,55.49 18.14,55.51
  Bottom 0.406: X5.2 18.1,55.22 18.12,55.24
N$26  (via drill 0.61)
  Top 0.254: v33.36,60.83 37.94,60.83 IC4.14
  Bottom 0.254: 21.93,66.67 X2.3
  Bottom 0.406: v33.36,60.83 30.57,63.62 24.98,63.62 21.93,66.67
N$27  (via drill 0.61)
  Top 0.254: v53.56,56.26 44.41,56.26 IC4.8
  Bottom 0.406: v53.56,56.26 57.37,60.07 57.37,66.16 X3.2
N$28  (via drill 0.61)
  Top 0.254: v45.43,58.8 43.14,58.8 43.14,58.03 IC4.7
  Bottom 0.254: v45.43,58.8 44.92,58.8
  Bottom 0.406: 44.92,58.8 43.9,59.81 43.9,62.35 46.32,64.77 53.05,64.77 X3.3
N$33
  Bottom 0.406: 55.97,51.3 C23.2 R4.1
N$35
  Bottom 0.254: 60.92,48.38 60.92,45.97 62.37,44.52 U1.63
  Bottom 0.406: 60.92,48.38 C22.2 59.51,51.29 59.52,51.3 R4.2
PA0
  Bottom 0.254: U1.48 66.57,26.22 80.1,12.7 SV2.4
PA1
  Bottom 0.254: 97.12,15.24 SV2.5 82.39,15.24 78.7,15.24 67.07,26.74 U1.47
PA2
  Bottom 0.254: 97.12,17.65 SV2.6 83.78,17.77 76.29,25.27 73.75,25.27 68.57,30.45 U1.44
PA3
  Bottom 0.254: 97.12,20.31 SV2.7 | 97.12,20.31 85.31,20.31 79.72,25.9 73.88,25.9 69.07,30.71 U1.43 | 97.12,20.31 97.24,20.19
PA4
  Bottom 0.254: U1.36 72.57,33.81 73.37,33.02 94.45,33.02 96.36,34.92 SV3.4
PA5  (via drill 0.61)
  Top 0.254: v56.1,65.4 58.64,65.4 59.91,64 77.18,64 80.99,60.32 92.67,48.64 92.67,37.59 91.91,36.83 v91.91,34.92
  Bottom 0.254: v56.1,65.4 53.81,63.11 JP2.3 | v91.91,34.92 90.64,33.65 73.5,33.65 73.07,34.08 U1.35
PA6  (via drill 0.61)
  Top 0.254: v64.22,65.4 64.73,64.89 77.81,64.89 93.43,49.27 v93.43,36.19
  Bottom 0.254: v64.22,65.4 54.06,55.24 52.79,55.24 50.76,57.27 50.76,58.29 51.65,59.18 53.68,59.18 54.32,59.81 54.32,60.83 53.56,61.59 51.02,61.59 50,62.61 JP1.3 | U1.34 73.57,34.46 73.88,34.16 89.5,34.16 91.53,36.19 v93.43,36.19
PA7
  Bottom 0.254: U1.32 96.93,37.52 SV3.5
PA8
  Bottom 0.254: U1.31 94.25,38.02 96.23,40 SV3.6
PA9  (via drill 0.61)
  Top 0.254: v56.1,60.32 69.94,60.32 72.22,58.03 72.22,51.68 74.38,49.53 89.88,49.53 91.02,48.38 91.02,44.7 90,43.68 v90,38.98
  Bottom 0.254: v56.1,60.32 53.81,58.03 JP2.1 | U1.30 89.54,38.52 v90,38.98
PA10  (via drill 0.61)
  Top 0.254: v87.21,39.62 74.89,27.3 68.03,27.3 67.4,27.93 67.4,30.35 64.73,33.02 59.02,33.02 55.71,36.32 55.71,48 v51.52,52.19
  Bottom 0.254: v51.52,52.19 50.51,52.19 48.73,53.97 JP1.1 | 86.59,39.1 86.45,38.98 | v87.21,39.62 86.59,39.1 | 86.59,39.1 86.58,39.11 86.48,39.02 U1.29
PA11  (via drill 0.61)
  Top 0.254: 36.92,29.59 34,29.59 34,24.25 31.2,24.25 SD1.P$1 | 36.92,29.59 54.95,29.59 61.56,22.98 75.02,22.98 89.12,37.08 90.77,37.08 91.28,37.71 v91.28,42.54 | 36.92,29.59 R14.1
  Bottom 0.254: SV3.7 v91.28,42.54 88.48,42.54 85.46,39.52 U1.28
PA12  (via drill 0.61)
  Top 0.254: SD1.P$7 31.2,39.24 48.09,39.24 55.08,32.13 64.35,32.13 66.64,29.97 66.64,27.17 67.4,26.41 75.53,26.41 88.35,39.24 88.35,42.29 v87.59,43.05
  Bottom 0.254: 84.86,40.2 84.69,40.02 | v87.59,43.05 84.86,40.2 | v87.59,43.05 89.88,45.21 SV3.8 | v87.59,43.05 88.35,43.56 | 84.86,40.2 84.8,40.25 84.56,40.02 U1.27
PA13  (via drill 0.61)
  Top 0.254: SD1.P$2 25.62,26.73 25.62,20.31 32.6,20.31 35.27,22.98 45.3,22.98 52.54,15.74 52.54,12.95 55.33,10.16 79.97,10.16 94.83,25.01 v94.83,57.02
  Bottom 0.254: 97.12,57.78 SV1.4 95.08,57.78 | 95.08,57.78 94.83,57.78 90.13,53.08 90.13,50.54 84.8,45.21 82.26,45.21 79.57,42.52 U1.22 | v94.83,57.02 95.08,57.78
PA14  (via drill 0.61)
  Top 0.254: SD1.P$5 38.88,34.23 42.51,30.6 55.08,30.6 61.56,24.12 74.51,24.12 88.99,38.6 88.99,43.43 v84.54,47.87
  Bottom 0.254: 84.29,48.13 96.48,60.32 SV1.5 97.12,60.32 | v84.54,47.87 84.29,48.13 | U1.21 79.18,43.02 84.29,48.13
PA15
  Bottom 0.254: 78.7,43.56 94.83,59.69 94.83,60.7 SV1.6 | 78.7,43.56 78.7,43.52 | U1.20 78.67,43.52 78.7,43.56
PA16  (via drill 0.61)
  Top 0.406: R16.2 25.55,45.27 24.6,44.32 19.39,44.32 16.98,46.73 16.98,61.21 14.06,64.13 14.06,70.73 16.73,73.4 84.54,73.4 v94.07,63.88
  Bottom 0.254: 78.19,44.06 78.19,44.02 | 78.19,44.06 94.07,59.94 94.07,62.99 94.51,63.43 96.48,65.4 SV1.7 | U1.19 78.15,44.02 78.19,44.06
  Bottom 0.406: 94.58,63.37 94.51,63.43 v94.07,63.88
PA17
  Bottom 0.254: U1.9 70.57,54.35 73.24,57.02 73.24,62.1 84.29,73.15 AD.6 84.16,75.31
PA18
  Bottom 0.254: U1.10 71.08,46.98 71.08,53.59 74.13,56.64 74.13,60.96 86.96,73.78 AD.5
PA19
  Bottom 0.254: AD.4 89.37,74.42 84.67,69.72 75.34,60.26 75.34,54.03 75.27,53.97 74.77,53.46 74.77,51.94 72.57,49.74 U1.13
PA20
  Bottom 0.254: 74.13,48.89 75.27,50.03 76.03,50.03 91.66,65.65 91.66,75.56 AD.3 | U1.16 74.07,48.83 74.13,48.89 | 74.13,48.89 74.13,48.76
PA21  (via drill 0.61)
  Top 0.254: IC4.9 44.41,64.38 44.41,64.64 45.05,65.27 54.19,65.27 55.08,64.38 58.38,64.38 59.4,63.37 68.92,63.37 73.88,58.54 v73.88,54.35
  Bottom 0.254: U1.11 71.57,52.17 v73.88,54.35
PA22  (via drill 0.61)
  Top 0.254: IC4.10 43.02,61.34 44.67,61.34 47.71,64.38 53.68,64.38 55.21,62.86 58.38,62.86 59.52,61.72 69.56,61.72 72.86,58.41 72.86,53.21 73.11,52.95 v76.03,52.95
  Bottom 0.254: v76.03,52.95 76.03,52.32 73.07,49.35 U1.14
PA23
  Bottom 0.254: SV1.8 95.59,69.34 95.59,77.08 95.21,77.59 91.15,77.59 90.64,76.96 90.64,66.16 73.57,49.09 U1.15
PA24  (via drill 0.61)
  Top 0.254: R10.2 28.16,47.11 28.16,49.91 R11.1 27.65,50.92 27.14,51.43 27.14,64.38 31.71,68.96 31.71,69.21 34,71.5 73.88,71.5 80.48,64.89 80.48,64.64 v91.91,53.21
  Bottom 0.254: 92.16,52.95 91.02,51.81 91.02,50.54 85.05,44.57 83.15,44.57 80.59,42.02 U1.23 | 92.16,52.95 94.45,55.24 97.12,55.24 | 97.12,55.24 SV1.3 | 97.12,55.24 97.24,55.11 | v91.91,53.21 92.16,52.95
PA25
  Bottom 0.254: 97.12,52.7 SV1.2 94.58,52.7 82.9,41.02 U1.25
PA26
  Bottom 0.254: 97.12,50.16 SV1.1 93.05,50.16 83.53,40.64 83.41,40.52 U1.26
PA27
  Bottom 0.254: SV3.3 72.99,32.38 72.07,33.3 U1.37
PA28
  Bottom 0.254: U1.38 71.57,33.04 72.99,31.62 94.58,31.62 96.36,29.84 SV3.2
PA29
  Bottom 0.254: U1.41 70.07,31.49 74.26,27.3 80.61,27.3 82.39,25.52 90.26,25.52 92.04,27.3 SV3.1
PA30
  Bottom 0.254: 97.12,22.86 SV2.8 94.96,24.89 94.83,24.89 81.88,24.89 80.23,26.54 74.13,26.54 69.57,31.1 U1.42
PA31  (via drill 0.61)
  Top 0.254: v52.03,38.1 48.22,42.03 31.2,42.03 SD1.P$11 | v65.11,25.39 62.19,28.44 59.27,28.44 v57.87,29.84
  Bottom 0.254: 57.87,33.65 56.6,33.65 v52.03,38.1 | 57.87,33.65 57.87,36.57 60.32,39.02 U1.52 | 57.87,30.09 v57.87,29.84 57.87,33.65 | SV2.3 81.62,10.16 66.26,25.39 v65.11,25.39
R1OUT  (via drill 0.3 pad 1.02)
  Top 0.254: v46.44,59.69 41.11,59.69 40.48,60.32 IC4.12
  Bottom 0.254: JP2.2 51.65,60.32 50.38,59.05 47.08,59.05 v46.44,59.69
RST  (via drill 0.41 pad 1.02)
  Top 0.254: R2.1 36.54,7.74 S2.4 | v82.51,28.32 82.51,25.65 76.67,19.93 70.95,19.93 68.16,17.14 68.16,12.82 66.89,11.55 57.37,11.55 v54.32,14.6
  Bottom 0.254: S2.4 37.43,8.25 42.25,8.25 S2.3 54.32,8.3 | 56.48,6.85 JTAG1.15 55.03,8.3 54.32,8.3 | U1.39 71.07,32.39 72.86,30.6 80.23,30.6 v82.51,28.32 | 54.32,8.3 v54.32,14.6
T1IN  (via drill 0.3 pad 1.02)
  Top 0.254: v46.57,61.46 46.32,61.46 45.43,60.57 42.13,60.57 41.74,60.96 IC4.11
  Bottom 0.254: JP1.2 47.71,60.32 v46.57,61.46
TCK
  Bottom 0.254: JTAG1.9 JTAG1.11 60.67,6.98 59.4,5.71 58.38,5.71 57.62,6.34 57.62,8.12 56.35,9.77 56.35,23.49 | 56.35,23.49 61.94,17.9 R12.1 | 56.35,23.49 50.76,29.08 43.78,29.08 43.78,33.65 50.76,33.65 50.76,39.24 54.06,39.24 55.08,38.35 58.64,38.35 59.81,39.52 U1.53
TDI  (via drill 0.61)
  Top 0.254: v89.24,35.55 89.24,24 81.88,16.63 v71.34,16.63
  Bottom 0.254: R6.2 68.67,16.76 69.05,16.76 69.05,16.63 | JTAG1.5 69.05,16.63 | U1.33 88.08,35.57 v89.24,35.55 | 69.05,16.63 v71.34,16.63
TDO  (via drill 0.61)
  Top 0.254: v58.38,14.85 v62.45,18.92
  Bottom 0.254: v62.45,18.92 62.45,37.46 62.51,37.52 U1.49 | v58.38,14.85 58.38,12.82 R8.2 58.38,11.3 58.64,11.04 58.64,7.49 JTAG1.13
TMS  (via drill 0.61)
  Top 0.254: v58.89,24 65.49,17.39 v65.49,13.84
  Bottom 0.254: v58.89,24 58.89,27.55 60.92,29.59 60.92,38.48 60.97,38.52 U1.51 | v65.49,13.84 66.51,12.82 R7.2 66.26,11.3 66.26,7.49 JTAG1.7
USB_5V
  Top 0.254: R10.1 30.19,45.59 29.55,44.83 27.65,44.83 10.88,28.06 10.88,15.36 D3.A
  Bottom 0.254: X5.1 13.68,52.19 13.68,18.16 10.88,15.36 D3.A

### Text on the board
Top: AT91SAM7 Top
Bottom: AT91SAM7 Bottom
Document: AD4 | AD6 | AD7 | PA19 AD2 | AD5 | PA17 AD0 | PA18 AD1 | PA20 AD3 | 3,3V | GND | PA23 | PA16 | PA15 | PA14 | PA13 | PA24 | PA25 | PA26 | PA12 | PA11 | PA8 | PA7 | PA4 | PA27 | PA28 | PA29 | PA30 | PA3 | PA2 | PA1 | Reset | PA0 | 3,3V | PA31 | PWR IN | GND | GND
